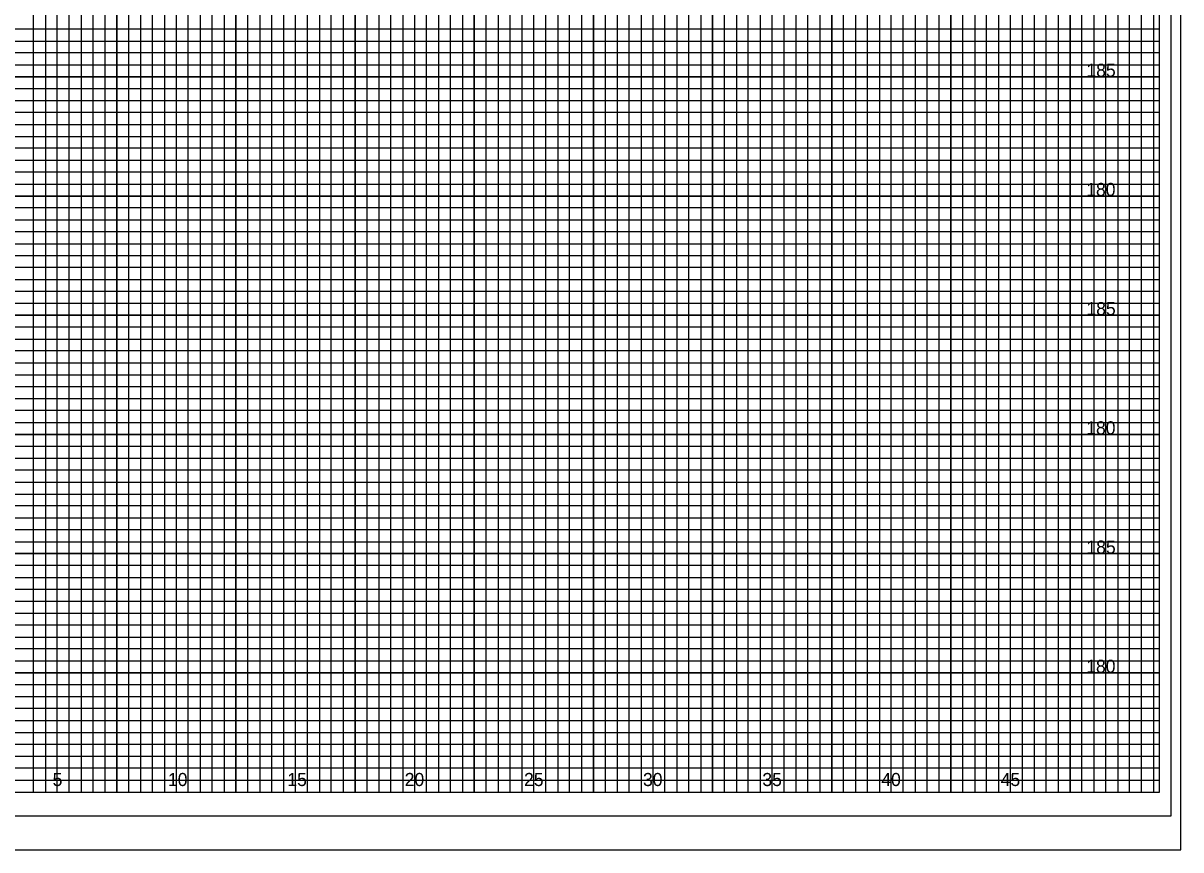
# Model space of a CAD drawing. Extents: x -4 to 103, y -2 to 6583.
# Drawn here: x 54.82 to 103.4, y 564.18 to 598.85 of the extents above; entities that cross this region are included whole.
import ezdxf

# ---------------------------------------------------------------- set-up
doc = ezdxf.new("R2010")
doc.units = 0
for name, color, linetype in [('Prop XS Elevation Labels', 7, 'Continuous'), ('Prop XS Offset Labels', 7, 'Continuous'), ('Sheet Cross Section CELL', 7, 'Continuous'), ('Sheet Cross Section Grid Major CELL', 7, 'Continuous'), ('Sheet Cross Section Grid Middle CELL', 7, 'Continuous'), ('Sheet Cutting Line CELL', 7, 'Continuous'), ('Sheet DOT Grid CELL', 7, 'Continuous'), ('Sheet Plot Border Inside CELL', 7, 'Continuous'), ('Sheet Plot Border Outside CELL', 7, 'Continuous')]:
    doc.layers.add(name, color=color, linetype=linetype)

msp = doc.modelspace()

# ---------------------------------------------------------------- linework, layer by layer
at = {"layer": 'Sheet Cross Section CELL'}
msp.add_lwpolyline([(102.5, 631.6), (0, 631.6), (0, 566.6), (102.5, 566.6)], close=True, dxfattribs=at)
at = {"layer": 'Sheet Cross Section Grid Major CELL'}
for points in [[(56.25, 566.6), (56.25, 631.6)], [(58.75, 631.6), (58.75, 566.6), (61.25, 566.6), (61.25, 631.6)], [(63.75, 631.6), (63.75, 566.6), (66.25, 566.6), (66.25, 631.6)], [(68.75, 631.6), (68.75, 566.6), (71.25, 566.6), (71.25, 631.6)], [(73.75, 631.6), (73.75, 566.6), (76.25, 566.6), (76.25, 628.6)], [(88.75, 628.6), (88.75, 566.6), (91.25, 566.6), (91.25, 630.025)], [(93.75, 630.025), (93.75, 566.6), (96.25, 566.6), (96.25, 630.025)], [(98.75, 630.025), (98.75, 566.6), (101.25, 566.6), (101.25, 630.025)], [(78.75, 628.6), (78.75, 566.6), (81.25, 566.6), (81.25, 628.6)], [(83.75, 628.6), (83.75, 566.6), (86.25, 566.6), (86.25, 628.6)], [(0, 594.1), (102.5, 594.1), (102.5, 596.6), (0, 596.6)], [(0, 589.1), (102.5, 589.1), (102.5, 591.6), (0, 591.6)], [(0, 584.1), (102.5, 584.1), (102.5, 586.6), (0, 586.6)], [(0, 579.1), (102.5, 579.1), (102.5, 581.6), (0, 581.6)], [(0, 574.1), (102.5, 574.1), (102.5, 576.6), (0, 576.6)], [(0, 569.1), (102.5, 569.1), (102.5, 571.6), (0, 571.6)]]:
    msp.add_lwpolyline(points, dxfattribs=at)
at = {"layer": 'Sheet Cross Section Grid Middle CELL'}
for points in [[(54.75, 566.6), (55.25, 566.6), (55.25, 631.6)], [(55.75, 631.6), (55.75, 566.6), (56.75, 566.6), (56.75, 631.6)], [(57.25, 631.6), (57.25, 566.6), (57.75, 566.6), (57.75, 631.6)], [(58.25, 631.6), (58.25, 566.6), (59.25, 566.6), (59.25, 631.6)], [(59.75, 631.6), (59.75, 566.6), (60.25, 566.6), (60.25, 631.6)], [(60.75, 631.6), (60.75, 566.6), (61.75, 566.6), (61.75, 631.6)], [(62.25, 631.6), (62.25, 566.6), (62.75, 566.6), (62.75, 631.6)], [(63.25, 631.6), (63.25, 566.6), (64.25, 566.6), (64.25, 631.6)], [(64.75, 631.6), (64.75, 566.6), (65.25, 566.6), (65.25, 631.6)], [(65.75, 631.6), (65.75, 566.6), (66.75, 566.6), (66.75, 631.6)], [(67.25, 631.6), (67.25, 566.6), (67.75, 566.6), (67.75, 631.6)], [(68.25, 631.6), (68.25, 566.6), (69.25, 566.6), (69.25, 631.6)], [(69.75, 631.6), (69.75, 566.6), (70.25, 566.6), (70.25, 631.6)], [(70.75, 631.6), (70.75, 566.6), (71.75, 566.6), (71.75, 631.6)], [(72.25, 631.6), (72.25, 566.6), (72.75, 566.6), (72.75, 631.6)], [(73.25, 631.6), (73.25, 566.6), (74.25, 566.6), (74.25, 628.6)], [(89.75, 628.6), (89.75, 566.6), (90.25, 566.6), (90.25, 630.025)], [(90.75, 630.025), (90.75, 566.6), (91.75, 566.6), (91.75, 630.025)], [(92.25, 630.025), (92.25, 566.6), (92.75, 566.6), (92.75, 630.025)], [(93.25, 630.025), (93.25, 566.6), (94.25, 566.6), (94.25, 630.025)], [(94.75, 630.025), (94.75, 566.6), (95.25, 566.6), (95.25, 630.025)], [(95.75, 630.025), (95.75, 566.6), (96.75, 566.6), (96.75, 630.025)], [(97.25, 630.025), (97.25, 566.6), (97.75, 566.6), (97.75, 630.025)], [(98.25, 630.025), (98.25, 566.6), (99.25, 566.6), (99.25, 630.025)], [(99.75, 630.025), (99.75, 566.6), (100.25, 566.6), (100.25, 630.025)], [(100.25, 630.025), (100.75, 630.025), (100.75, 566.6), (101.75, 566.6), (101.75, 630.025), (102.25, 630.025), (102.25, 566.6)], [(74.75, 628.6), (74.75, 566.6), (75.25, 566.6), (75.25, 628.6)], [(75.75, 628.6), (75.75, 566.6), (76.75, 566.6), (76.75, 628.6)], [(77.25, 628.6), (77.25, 566.6), (77.75, 566.6), (77.75, 628.6)], [(78.25, 628.6), (78.25, 566.6), (79.25, 566.6), (79.25, 628.6)], [(79.75, 628.6), (79.75, 566.6), (80.25, 566.6), (80.25, 628.6)], [(80.75, 628.6), (80.75, 566.6), (81.75, 566.6), (81.75, 628.6)], [(82.25, 628.6), (82.25, 566.6), (82.75, 566.6), (82.75, 628.6)], [(83.25, 628.6), (83.25, 566.6), (84.25, 566.6), (84.25, 628.6)], [(84.75, 628.6), (84.75, 566.6), (85.25, 566.6), (85.25, 628.6)], [(85.75, 628.6), (85.75, 566.6), (86.75, 566.6), (86.75, 628.6)], [(87.25, 628.6), (87.25, 566.6), (87.75, 566.6), (87.75, 628.6)], [(88.25, 628.6), (88.25, 566.6), (89.25, 566.6), (89.25, 628.6)], [(0, 598.1), (102.5, 598.1), (102.5, 598.6), (0, 598.6)], [(0, 597.1), (102.5, 597.1), (102.5, 597.6), (0, 597.6)], [(0, 595.6), (102.5, 595.6), (102.5, 596.1), (0, 596.1)], [(0, 594.6), (102.5, 594.6), (102.5, 595.1), (0, 595.1)], [(0, 593.1), (102.5, 593.1), (102.5, 593.6), (0, 593.6)], [(0, 592.1), (102.5, 592.1), (102.5, 592.6), (0, 592.6)], [(0, 590.6), (102.5, 590.6), (102.5, 591.1), (0, 591.1)], [(0, 589.6), (102.5, 589.6), (102.5, 590.1), (0, 590.1)], [(0, 588.1), (102.5, 588.1), (102.5, 588.6), (0, 588.6)], [(0, 587.1), (102.5, 587.1), (102.5, 587.6), (0, 587.6)], [(0, 585.6), (102.5, 585.6), (102.5, 586.1), (0, 586.1)], [(0, 584.6), (102.5, 584.6), (102.5, 585.1), (0, 585.1)], [(0, 583.1), (102.5, 583.1), (102.5, 583.6), (0, 583.6)], [(0, 582.1), (102.5, 582.1), (102.5, 582.6), (0, 582.6)], [(0, 580.6), (102.5, 580.6), (102.5, 581.1), (0, 581.1)], [(0, 579.6), (102.5, 579.6), (102.5, 580.1), (0, 580.1)], [(0, 578.1), (102.5, 578.1), (102.5, 578.6), (0, 578.6)], [(0, 577.1), (102.5, 577.1), (102.5, 577.6), (0, 577.6)], [(0, 575.6), (102.5, 575.6), (102.5, 576.1), (0, 576.1)], [(0, 574.6), (102.5, 574.6), (102.5, 575.1), (0, 575.1)], [(0, 573.1), (102.5, 573.1), (102.5, 573.6), (0, 573.6)], [(0, 572.1), (102.5, 572.1), (102.5, 572.6), (0, 572.6)], [(0, 570.6), (102.5, 570.6), (102.5, 571.1), (0, 571.1)], [(0, 569.6), (102.5, 569.6), (102.5, 570.1), (0, 570.1)], [(0, 568.1), (102.5, 568.1), (102.5, 568.6), (0, 568.6)], [(0, 567.1), (102.5, 567.1), (102.5, 567.6), (0, 567.6)]]:
    msp.add_lwpolyline(points, dxfattribs=at)
at = {"layer": 'Sheet Cutting Line CELL'}
msp.add_line((-3.5, 564.175), (103.4, 564.175), dxfattribs=at)
at = {"layer": 'Sheet DOT Grid CELL'}
for p, q in [((56.25, 566.6), (56.25, 631.6)), ((58.75, 566.6), (58.75, 631.6)), ((61.25, 566.6), (61.25, 631.6)), ((63.75, 566.6), (63.75, 631.6)), ((66.25, 566.6), (66.25, 631.6)), ((68.75, 566.6), (68.75, 631.6)), ((71.25, 566.6), (71.25, 631.6)), ((73.75, 566.6), (73.75, 631.6)), ((91.25, 566.6), (91.25, 630.025)), ((93.75, 566.6), (93.75, 630.025)), ((96.25, 566.6), (96.25, 630.025)), ((98.75, 566.6), (98.75, 630.025)), ((101.25, 566.6), (101.25, 630.025)), ((76.25, 566.6), (76.25, 628.6)), ((78.75, 566.6), (78.75, 628.6)), ((81.25, 566.6), (81.25, 628.6)), ((83.75, 566.6), (83.75, 628.6)), ((86.25, 566.6), (86.25, 628.6)), ((88.75, 566.6), (88.75, 628.6)), ((0, 596.6), (102.5, 596.6)), ((0, 594.1), (102.5, 594.1)), ((0, 591.6), (102.5, 591.6)), ((0, 589.1), (102.5, 589.1)), ((0, 586.6), (102.5, 586.6)), ((0, 584.1), (102.5, 584.1)), ((0, 581.6), (102.5, 581.6)), ((0, 579.1), (102.5, 579.1)), ((0, 576.6), (102.5, 576.6)), ((0, 574.1), (102.5, 574.1)), ((0, 571.6), (102.5, 571.6)), ((0, 569.1), (102.5, 569.1))]:
    msp.add_line(p, q, dxfattribs=at)
at = {"layer": 'Sheet Plot Border Inside CELL'}
msp.add_lwpolyline([(103, 632.6), (-2.8, 632.6), (-2.8, 565.6), (103, 565.6)], close=True, dxfattribs=at)
at = {"layer": 'Sheet Plot Border Outside CELL'}
msp.add_lwpolyline([(103.4, 634), (-3.5, 634), (-3.5, 564.175), (103.4, 564.175)], close=True, dxfattribs=at)

# ---------------------------------------------------------------- texts
at = {"layer": 'Prop XS Elevation Labels'}
for s, p in [('185', (99.438, 596.6)), ('180', (99.43, 591.6)), ('185', (99.438, 586.6)), ('180', (99.43, 581.6)), ('185', (99.438, 576.6)), ('180', (99.43, 571.6))]:
    msp.add_text(s, height=0.55, dxfattribs=at).set_placement(p)
at = {"layer": 'Prop XS Offset Labels'}
for s, p in [('5', (56.057, 566.85)), ('10', (60.897, 566.85)), ('15', (65.906, 566.85)), ('20', (70.831, 566.85)), ('25', (75.84, 566.85)), ('30', (80.831, 566.85)), ('35', (85.84, 566.85)), ('40', (90.831, 566.85)), ('45', (95.84, 566.85))]:
    msp.add_text(s, height=0.55, dxfattribs=at).set_placement(p)

doc.saveas('drawing.dxf')
